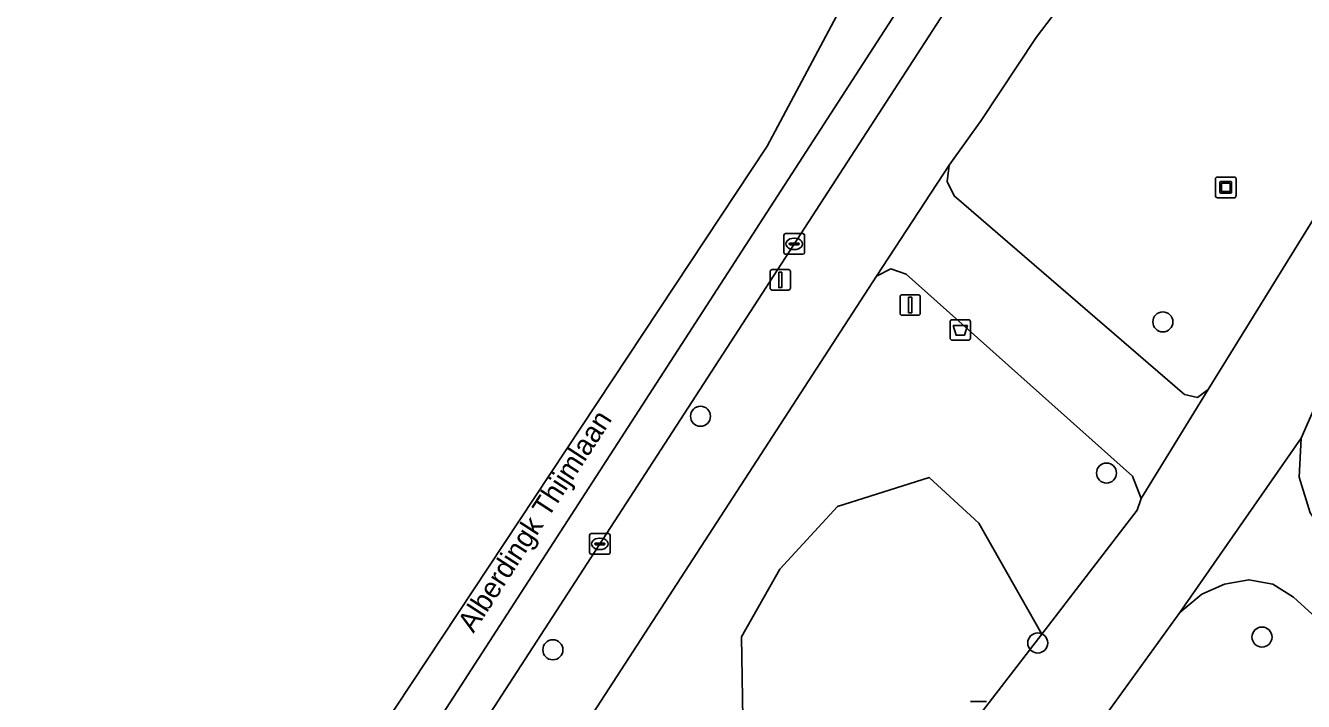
# Model space of a CAD drawing. Extents: x 161402 to 161933, y 381647 to 382315.
# Drawn here: x 161525.1 to 161587.5, y 382042.9 to 382075.9 of the extents above; entities that cross this region are included whole.
import ezdxf

# ---------------------------------------------------------------- set-up
doc = ezdxf.new("R2010")
doc.units = 0
for name, color, linetype in [('IMGEO_Afvalbak', 7, 'Continuous'), ('IMGEO_Boom', 7, 'Continuous'), ('IMGEO_Groenvoorziening', 7, 'Continuous'), ('IMGEO_Kolk', 7, 'Continuous'), ('IMGEO_Kunstobject', 7, 'Continuous'), ('IMGEO_Lichtmast', 7, 'Continuous'), ('IMGEO_Openbare_ruimte_label', 7, 'Continuous'), ('IMGEO_Rijbaan_lokaal_gesloten', 7, 'Continuous'), ('IMGEO_Rijbaan_lokaal_open', 7, 'Continuous'), ('IMGEO_Verkeersbordpaal', 7, 'Continuous'), ('IMGEO_Voetpad_gesloten', 7, 'Continuous'), ('IMGEO_Voetpad_open', 7, 'Continuous')]:
    doc.layers.add(name, color=color, linetype=linetype)

msp = doc.modelspace()

# ---------------------------------------------------------------- linework, layer by layer
at = {"layer": 'IMGEO_Afvalbak'}
for p, q in [((161570.226, 382060.657), (161570.226, 382061.457)), ((161570.226, 382061.457), (161570.226, 382060.657)), ((161570.326, 382061.557), (161571.116, 382061.557)), ((161571.116, 382061.557), (161570.326, 382061.557)), ((161571.216, 382061.457), (161571.216, 382060.657)), ((161571.216, 382060.657), (161571.216, 382061.457)), ((161571.116, 382060.557), (161570.326, 382060.557)), ((161570.326, 382060.557), (161571.116, 382060.557))]:
    msp.add_line(p, q, dxfattribs=at)
msp.add_lwpolyline([(161570.369, 382061.271), (161571.073, 382061.271), (161570.924, 382060.801), (161570.518, 382060.801), (161570.369, 382061.271)], dxfattribs=at)
for centre, start, end in [((161570.326, 382061.457), 90, 180), ((161570.326, 382061.457), 90, 180), ((161571.116, 382061.457), 0, 90), ((161571.116, 382061.457), 360, 90), ((161570.326, 382060.657), 180, 270), ((161570.326, 382060.657), 180, 270), ((161571.116, 382060.657), 270, 0), ((161571.116, 382060.657), 270, 0)]:
    msp.add_arc(centre, 0.1, start, end, dxfattribs=at)
at = {"layer": 'IMGEO_Boom'}
for centre in [(161580.604, 382061.45), (161558.047, 382056.845), (161577.855, 382054.076), (161574.5, 382045.785), (161585.441, 382046.074), (161550.846, 382045.454)]:
    msp.add_circle(centre, 0.489, dxfattribs=at)
at = {"layer": 'IMGEO_Groenvoorziening'}
for points in [[(161608.435, 382119.953), (161574.421, 382075.333), (161571.745, 382071.279), (161570.174, 382069.09), (161570.085, 382068.306), (161570.428, 382067.596), (161581.666, 382057.913), (161582.301, 382057.757), (161582.818, 382058.156), (161592.764, 382074.245), (161598.47, 382083.033), (161608.254, 382097.285), (161612.452, 382102.646), (161616.48, 382107.434), (161620.728, 382112.027), (161610.839, 382118.38)], [(161566.397, 382035.429), (161574.693, 382046.208), (161571.62, 382051.637), (161569.199, 382053.861), (161564.736, 382052.445), (161561.918, 382049.386), (161560.053, 382046.091), (161560.125, 382041.115), (161561.912, 382038.8)]]:
    msp.add_lwpolyline(points, close=True, dxfattribs=at)
for points in [[(161595.302, 382064.992), (161592.51, 382064.912), (161588.122, 382057.524), (161587.35, 382055.783), (161587.259, 382053.881), (161587.788, 382052.14), (161588.839, 382050.654), (161618.822, 382023.52), (161622.522, 382027.703), (161621.506, 382036.425), (161619.567, 382036.081), (161619.036, 382038.731), (161618.459, 382043.171), (161618.607, 382047.031), (161620.259, 382047.132), (161618.437, 382062.782), (161613.557, 382064.703)], [(161550.139, 382016.903), (161566.397, 382035.429), (161561.912, 382038.8), (161560.125, 382041.115), (161560.053, 382046.091), (161561.918, 382049.386), (161564.736, 382052.445), (161569.199, 382053.861), (161571.62, 382051.637), (161574.693, 382046.208), (161579.356, 382052.267), (161579.545, 382052.829), (161579.122, 382053.921), (161568.086, 382063.783), (161567.337, 382064.038), (161566.628, 382063.688), (161525.324, 382000), (161509.956, 381976.304), (161510.352, 381976.047), (161510.195, 381975.805), (161512.522, 381974.297), (161512.354, 381974.043)], [(161608.216, 382001.645), (161619.663, 382012.768), (161620.566, 382014.018), (161621.031, 382015.488), (161621.022, 382016.582), (161620.495, 382017.54), (161586.971, 382048.017), (161585.966, 382048.656), (161584.795, 382048.872), (161583.611, 382048.649), (161582.51, 382048.162), (161581.425, 382047.268), (161574.039, 382037.028), (161573.408, 382035.438), (161573.21, 382034.265), (161573.524, 382033.118), (161574.473, 382031.494), (161579.342, 382026.767), (161606.792, 382001.445)]]:
    msp.add_lwpolyline(points, dxfattribs=at)
at = {"layer": 'IMGEO_Kolk'}
for p, q in [((161562.118, 382064.83), (161562.118, 382065.682)), ((161562.193, 382065.756), (161563.045, 382065.756)), ((161562.606, 382065.536), (161562.631, 382065.536)), ((161563.119, 382065.682), (161563.119, 382064.83)), ((161563.045, 382064.756), (161562.193, 382064.756)), ((161562.377, 382065.25), (161562.377, 382065.262)), ((161562.815, 382065.213), (161562.417, 382065.213)), ((161562.42, 382065.299), (161562.818, 382065.299)), ((161562.629, 382064.976), (161562.604, 382064.976)), ((161562.861, 382065.262), (161562.861, 382065.25)), ((161552.636, 382050.194), (161552.636, 382051.046)), ((161552.711, 382051.12), (161553.563, 382051.12)), ((161553.637, 382051.046), (161553.637, 382050.194)), ((161552.895, 382050.614), (161552.895, 382050.626)), ((161553.333, 382050.577), (161552.935, 382050.577)), ((161552.938, 382050.663), (161553.336, 382050.663)), ((161553.124, 382050.9), (161553.149, 382050.9)), ((161553.379, 382050.626), (161553.379, 382050.614)), ((161553.563, 382050.12), (161552.711, 382050.12)), ((161553.147, 382050.34), (161553.122, 382050.34))]:
    msp.add_line(p, q, dxfattribs=at)
for points in [[(161562.118, 382064.83), (161562.118, 382065.682)], [(161562.193, 382065.756), (161563.045, 382065.756)], [(161563.119, 382065.682), (161563.119, 382064.83)], [(161563.045, 382064.756), (161562.193, 382064.756)], [(161552.636, 382050.194), (161552.636, 382051.046)], [(161552.711, 382051.12), (161553.563, 382051.12)], [(161553.637, 382051.046), (161553.637, 382050.194)], [(161553.563, 382050.12), (161552.711, 382050.12)]]:
    msp.add_lwpolyline(points, dxfattribs=at)
for centre, radius, start, end in [((161562.195, 382065.68), 0.0765, 91.55205, 178.44795), ((161562.195, 382065.68), 0.0765, 91.55205, 178.44795), ((161563.043, 382065.68), 0.0765, 1.55205, 88.44795), ((161563.043, 382065.68), 0.0765, 1.55205, 88.44795), ((161562.195, 382064.832), 0.0765, 181.55205, 268.44795), ((161562.195, 382064.832), 0.0765, 181.55205, 268.44795), ((161562.417, 382065.259), 0.0403, 85.87752, 175.75265), ((161562.414, 382065.249), 0.0366, 178.93798, 274.71019), ((161562.818, 382065.256), 0.043, 264.86636, 352.45326), ((161562.822, 382065.261), 0.0386, 1.73085, 96.63898), ((161563.043, 382064.832), 0.0765, 271.55205, 358.44795), ((161563.043, 382064.832), 0.0765, 271.55205, 358.44795), ((161552.713, 382051.044), 0.0765, 91.55205, 178.44795), ((161552.713, 382051.044), 0.0765, 91.55205, 178.44795), ((161553.561, 382051.044), 0.0765, 1.55205, 88.44795), ((161553.561, 382051.044), 0.0765, 1.55205, 88.44795), ((161552.935, 382050.623), 0.0403, 85.87752, 175.75265), ((161552.932, 382050.613), 0.0366, 178.93798, 274.71019), ((161553.336, 382050.62), 0.043, 264.86636, 352.45326), ((161553.34, 382050.625), 0.0386, 1.73085, 96.63898), ((161552.713, 382050.196), 0.0765, 181.55205, 268.44795), ((161552.713, 382050.196), 0.0765, 181.55205, 268.44795), ((161553.561, 382050.196), 0.0765, 271.55205, 358.44795), ((161553.561, 382050.196), 0.0765, 271.55205, 358.44795)]:
    msp.add_arc(centre, radius, start, end, dxfattribs=at)
for centre, major_axis, ratio, start_param, end_param in [((161562.605, 382065.256), (-0.387, 0.002), 0.722429, 4.712389, 7.853982), ((161562.63, 382065.256), (-0.39, 0.002), 0.717154, 1.570796, 4.712389), ((161553.123, 382050.62), (-0.387, 0.002), 0.722429, 4.712389, 7.853982), ((161553.148, 382050.62), (-0.39, 0.002), 0.717154, 1.570796, 4.712389)]:
    msp.add_ellipse(centre, major_axis=major_axis, ratio=ratio, start_param=start_param, end_param=end_param, dxfattribs=at)
at = {"layer": 'IMGEO_Kunstobject'}
for p, q in [((161584.089, 382068.511), (161583.248, 382068.511)), ((161584.089, 382068.511), (161583.248, 382068.511)), ((161584.173, 382067.595), (161584.173, 382068.436)), ((161584.173, 382067.595), (161584.173, 382068.436)), ((161583.173, 382068.427), (161583.173, 382067.586)), ((161583.173, 382068.427), (161583.173, 382067.586)), ((161583.387, 382067.775), (161583.387, 382068.249)), ((161583.437, 382068.299), (161583.911, 382068.299)), ((161583.467, 382068.199), (161583.467, 382067.825)), ((161583.861, 382068.219), (161583.487, 382068.219)), ((161583.881, 382067.825), (161583.881, 382068.199)), ((161583.961, 382068.249), (161583.961, 382067.775)), ((161583.257, 382067.511), (161584.098, 382067.511)), ((161583.257, 382067.511), (161584.098, 382067.511)), ((161583.911, 382067.725), (161583.437, 382067.725)), ((161583.487, 382067.805), (161583.861, 382067.805))]:
    msp.add_line(p, q, dxfattribs=at)
for centre, radius, start, end in [((161583.251, 382068.433), 0.0779, 92.4484, 184.28452), ((161583.251, 382068.433), 0.0779, 92.4484, 184.28452), ((161584.095, 382068.433), 0.0779, 2.4484, 94.28452), ((161584.095, 382068.433), 0.0779, 2.4484, 94.28452), ((161583.437, 382068.249), 0.05, 90, 180), ((161583.487, 382068.199), 0.02, 90, 180), ((161583.487, 382067.825), 0.02, 180, 270), ((161583.861, 382068.199), 0.02, 360, 90), ((161583.861, 382067.825), 0.02, 270, 0), ((161583.911, 382068.249), 0.05, 360, 90), ((161583.251, 382067.589), 0.0779, 182.4484, 274.28452), ((161583.251, 382067.589), 0.0779, 182.4484, 274.28452), ((161583.437, 382067.775), 0.05, 180, 270), ((161583.911, 382067.775), 0.05, 270, 0), ((161584.095, 382067.589), 0.0779, 272.4484, 4.28452), ((161584.095, 382067.589), 0.0779, 272.4484, 4.28452)]:
    msp.add_arc(centre, radius, start, end, dxfattribs=at)
at = {"layer": 'IMGEO_Lichtmast'}
for p, q in [((161561.443, 382063.101), (161561.443, 382063.901)), ((161561.443, 382063.901), (161561.443, 382063.101)), ((161561.543, 382064.001), (161562.333, 382064.001)), ((161562.333, 382064.001), (161561.543, 382064.001)), ((161562.433, 382063.901), (161562.433, 382063.101)), ((161562.433, 382063.101), (161562.433, 382063.901)), ((161562.333, 382063.001), (161561.543, 382063.001)), ((161561.543, 382063.001), (161562.333, 382063.001)), ((161571.214, 382042.934), (161572.004, 382042.934)), ((161572.004, 382042.934), (161571.214, 382042.934))]:
    msp.add_line(p, q, dxfattribs=at)
msp.add_lwpolyline([(161561.863, 382063.876), (161562.013, 382063.876), (161562.013, 382063.126), (161561.863, 382063.126), (161561.863, 382063.876)], dxfattribs=at)
for centre, start, end in [((161561.543, 382063.901), 90, 180), ((161561.543, 382063.901), 90, 180), ((161562.333, 382063.901), 0, 90), ((161562.333, 382063.901), 360, 90), ((161561.543, 382063.101), 180, 270), ((161561.543, 382063.101), 180, 270), ((161562.333, 382063.101), 270, 0), ((161562.333, 382063.101), 270, 0)]:
    msp.add_arc(centre, 0.1, start, end, dxfattribs=at)
at = {"layer": 'IMGEO_Rijbaan_lokaal_gesloten'}
msp.add_lwpolyline([(161574.317, 382086.95), (161539.75, 382033.486), (161541.352, 382032.43), (161576.388, 382086.507), (161578.467, 382089.284)], dxfattribs=at)
at = {"layer": 'IMGEO_Rijbaan_lokaal_open'}
msp.add_lwpolyline([(161586.04, 382116.528), (161583.53, 382111.715), (161561.301, 382070.022), (161537.898, 382034.67), (161538.128, 382034.523), (161539.75, 382033.486), (161574.317, 382086.95)], dxfattribs=at)
at = {"layer": 'IMGEO_Verkeersbordpaal'}
for p, q in [((161567.781, 382061.874), (161567.781, 382062.674)), ((161567.781, 382062.674), (161567.781, 382061.874)), ((161567.881, 382062.774), (161568.671, 382062.774)), ((161568.671, 382062.774), (161567.881, 382062.774)), ((161568.771, 382062.674), (161568.771, 382061.874)), ((161568.771, 382061.874), (161568.771, 382062.674)), ((161568.671, 382061.774), (161567.881, 382061.774)), ((161567.881, 382061.774), (161568.671, 382061.774))]:
    msp.add_line(p, q, dxfattribs=at)
msp.add_lwpolyline([(161568.201, 382062.649), (161568.351, 382062.649), (161568.351, 382061.899), (161568.201, 382061.899), (161568.201, 382062.649)], dxfattribs=at)
for centre, start, end in [((161567.881, 382062.674), 90, 180), ((161567.881, 382062.674), 90, 180), ((161568.671, 382062.674), 0, 90), ((161568.671, 382062.674), 360, 90), ((161567.881, 382061.874), 180, 270), ((161567.881, 382061.874), 180, 270), ((161568.671, 382061.874), 270, 0), ((161568.671, 382061.874), 270, 0)]:
    msp.add_arc(centre, 0.1, start, end, dxfattribs=at)
at = {"layer": 'IMGEO_Voetpad_gesloten'}
for points in [[(161627.348, 382107.722), (161627.457, 382107.89), (161620.837, 382112.195), (161620.728, 382112.027), (161616.48, 382107.434), (161612.452, 382102.646), (161608.254, 382097.285), (161598.47, 382083.033), (161592.764, 382074.245), (161582.818, 382058.156), (161579.545, 382052.829), (161579.356, 382052.267), (161574.693, 382046.208), (161566.397, 382035.429), (161567.213, 382029.55), (161574.039, 382037.028), (161581.425, 382047.268), (161587.35, 382055.783), (161588.122, 382057.524), (161592.51, 382064.912), (161594.145, 382067.66)], [(161647.46, 381998.336), (161644.811, 382000), (161631.093, 382012.414), (161629.601, 382013.765), (161620.28, 382022.201), (161618.822, 382023.52), (161588.839, 382050.654), (161587.788, 382052.14), (161587.259, 382053.881), (161587.35, 382055.783), (161581.425, 382047.268), (161582.51, 382048.162), (161583.611, 382048.649), (161584.795, 382048.872), (161585.966, 382048.656), (161586.971, 382048.017), (161620.495, 382017.54), (161626.268, 382012.248), (161639.885, 382000), (161640.252, 381999.67)]]:
    msp.add_lwpolyline(points, dxfattribs=at)
msp.add_lwpolyline([(161570.428, 382067.596), (161570.085, 382068.306), (161570.174, 382069.09), (161566.628, 382063.688), (161567.337, 382064.038), (161568.086, 382063.783), (161579.122, 382053.921), (161579.545, 382052.829), (161582.818, 382058.156), (161582.301, 382057.757), (161581.666, 382057.913)], close=True, dxfattribs=at)
at = {"layer": 'IMGEO_Voetpad_open'}
for points in [[(161525.324, 382000), (161566.628, 382063.688), (161570.174, 382069.09), (161571.745, 382071.279), (161574.421, 382075.333), (161608.435, 382119.953), (161605.683, 382121.518), (161591.922, 382103.449)], [(161578.467, 382089.284), (161576.388, 382086.507), (161541.352, 382032.43), (161540.784, 382031.553), (161532.638, 382018.971), (161532.049, 382018.061), (161507.226, 381979.8), (161499.199, 381967.336), (161498.606, 381966.417), (161490.128, 381953.282), (161489.562, 381952.406), (161448.908, 381889.474), (161447.556, 381887.381), (161443.733, 381881.365)]]:
    msp.add_lwpolyline(points, dxfattribs=at)

# ---------------------------------------------------------------- texts
at = {"layer": 'IMGEO_Openbare_ruimte_label'}
msp.add_text('Alberdingk Thijmlaan', height=1, rotation=57.04099, dxfattribs=at).set_placement((161546.972, 382046.232))

doc.saveas('drawing.dxf')
